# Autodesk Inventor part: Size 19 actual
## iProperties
Created: 2006-11
Part Number: Size 19 actual
Document SubType Name: Modeling
Designer: Andrew DuBuc
Density: 1 g/cm^3
Author: Andrew DuBuc
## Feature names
1. Revolution1
